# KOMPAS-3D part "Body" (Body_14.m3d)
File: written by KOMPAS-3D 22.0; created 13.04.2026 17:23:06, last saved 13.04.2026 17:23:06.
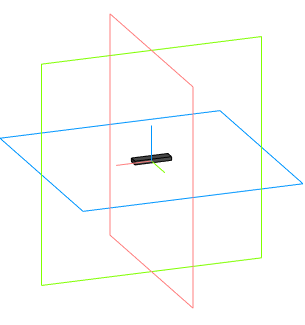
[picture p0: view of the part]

Document properties: Автор: Andrey; Полное имя файла: C:\Users\User1\Documents\Body_14.m3d

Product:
- Part/product: Body

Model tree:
1. Операция без истории:1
